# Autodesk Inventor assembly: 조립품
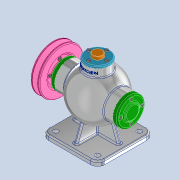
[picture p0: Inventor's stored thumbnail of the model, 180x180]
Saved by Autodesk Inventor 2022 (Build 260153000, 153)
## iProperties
Created: 2024-04
Part Number: 조립품
Document SubType Name: Assembly
Designer: Admin
Author: Admin
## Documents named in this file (16)
- C:\Users\Admin\Desktop\740406V1017(1)\조립품.iam
- C:\Users\Admin\Desktop\740406V1017(1)\부품.ipt
- C:\Users\Admin\Desktop\740406V1017(1)\740406V1017\뒤커버.ipt
- C:\Users\Admin\Desktop\740406V1017(1)\740406V1017\앞커버.ipt
- C:\Users\Admin\Desktop\740406V1017(1)\740406V1017\상부커버.ipt
- C:\Users\Admin\Desktop\740406V1017(1)\740406V1017\베어링- 6202.ipt
- KS B 2023 - 6202 - 15 x 35 x 11 - 7.8.ipt
- C:\Users\Admin\Desktop\740406V1017(1)\740406V1017\칼라.ipt
- C:\Users\Admin\Desktop\740406V1017(1)\740406V1017\편심축.ipt
- C:\Users\Admin\Desktop\740406V1017(1)\740406V1017\키 4 x 4 x 12.ipt
- C:\Users\Admin\Desktop\740406V1017(1)\740406V1017\오일실 15 30 7.ipt
- C:\Users\Admin\Desktop\740406V1017(1)\740406V1017\V-벨트풀리.ipt
- C:\Users\Admin\Desktop\740406V1017(1)\740406V1017\너트 M8.ipt
- C:\Users\Admin\Desktop\740406V1017(1)\740406V1017\볼트 M4 x 16.ipt
- C:\Users\Admin\Desktop\740406V1017(1)\740406V1017\볼트 M4 x 12.ipt
- C:\Users\Admin\Desktop\740406V1017(1)\740406V1017\슬라이드.ipt
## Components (15 placed, 4 different names)
1. KS B 2023 - 6202 - 15 x 35 x 11 - 7.8:1
2. KS B 2023 - 6202 - 15 x 35 x 11 - 7.8:2
3. V-벨트풀리:1
4. ISO 4762 M4 x 16:1
5. ISO 4762 M4 x 16:2
6. ISO 4762 M4 x 16:3
7. ISO 4762 M4 x 16:4
8. ISO 4762 M4 x 16:5
9. ISO 4762 M4 x 16:6
10. ISO 4762 M4 x 16:7
11. ISO 4762 M4 x 16:8
12. KS B 1021 - 에 따름 ISO 1207 - 미터 A  M 4 x 12:1
13. KS B 1021 - 에 따름 ISO 1207 - 미터 A  M 4 x 12:2
14. KS B 1021 - 에 따름 ISO 1207 - 미터 A  M 4 x 12:3
15. KS B 1021 - 에 따름 ISO 1207 - 미터 A  M 4 x 12:4
